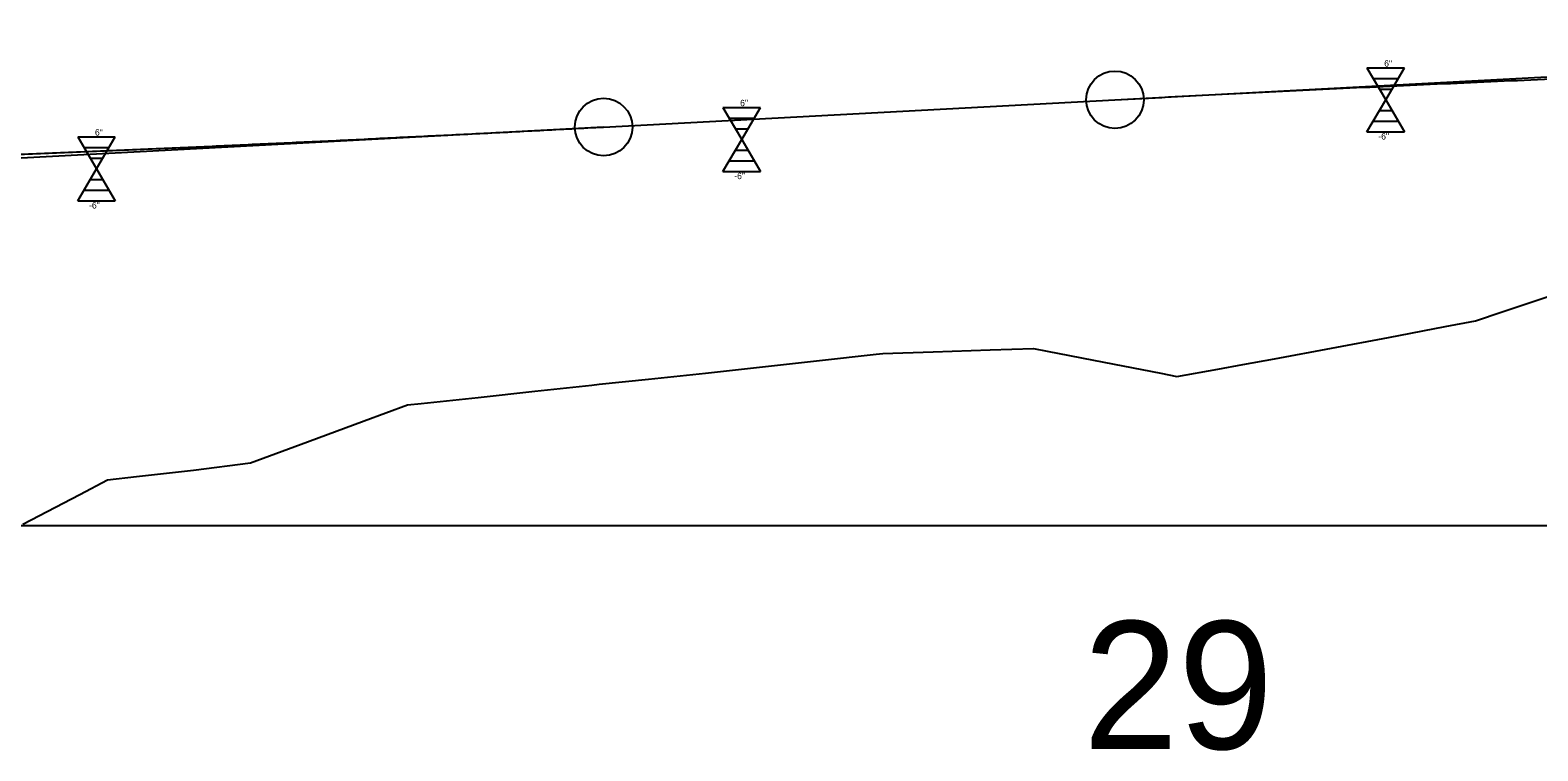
# Model space of a CAD drawing. Extents: x 573468 to 580768, y -57414 to -51768.
# Drawn here: x 575580.3 to 575698.2, y -53708.9 to -53652.5 of the extents above; entities that cross this region are included whole.
import ezdxf

# ---------------------------------------------------------------- set-up
doc = ezdxf.new("R2010")
doc.units = 0
for name, color, linetype in [('Exist Profile Cell', 7, 'Continuous'), ('Exist Vertical Profile Ground Line', 7, 'Continuous'), ('Exist Vertical Profile Horizontal Axis Label Major', 7, 'Continuous'), ('Pattern 2', 7, 'Continuous'), ('Prop Vertical Profile Curve Label', 7, 'Continuous'), ('Prop Vertical Profile Grade', 7, 'Continuous'), ('Prop VPI Label', 7, 'Continuous')]:
    doc.layers.add(name, color=color, linetype=linetype)

msp = doc.modelspace()

# ---------------------------------------------------------------- linework, layer by layer
at = {"layer": 'Exist Profile Cell'}
msp.add_line((573531.99, -53691.24), (576075.95, -53691.24), dxfattribs=at)
at = {"layer": 'Exist Vertical Profile Ground Line'}
msp.add_lwpolyline([(575579.69, -53691.16), (575584.14, -53688.82), (575586.3, -53687.68), (575588.59, -53687.43), (575593.04, -53686.93), (575597.49, -53686.34), (575601.95, -53684.71), (575606.4, -53683.07), (575609.78, -53681.8), (575610.85, -53681.7), (575615.3, -53681.23), (575619.75, -53680.75), (575624.2, -53680.26), (575624.78, -53680.19), (575628.65, -53679.79), (575633.11, -53679.32), (575637.56, -53678.84), (575642.01, -53678.34), (575646.46, -53677.84), (575646.96, -53677.78), (575650.91, -53677.66), (575655.36, -53677.51), (575658.77, -53677.39), (575659.82, -53677.6), (575664.27, -53678.48), (575668.72, -53679.34), (575669.98, -53679.58), (575673.17, -53679.01), (575675.14, -53678.66), (575677.62, -53678.21), (575682.07, -53677.38), (575686.53, -53676.54), (575690.98, -53675.69), (575693.33, -53675.23), (575695.43, -53674.53), (575699.88, -53673.04)], dxfattribs=at)
at = {"layer": 'Pattern 2'}
for p, q in [((575684.85, -53655.44), (575687.78, -53655.44)), ((575684.85, -53655.44), (575686.32, -53657.94)), ((575686.32, -53657.94), (575687.78, -53655.44)), ((575685.34, -53656.28), (575687.29, -53656.28)), ((575684.85, -53660.44), (575686.32, -53657.94)), ((575685.83, -53657.11), (575686.81, -53657.11)), ((575686.32, -53657.94), (575687.78, -53660.44)), ((575634.46, -53658.54), (575637.39, -53658.54)), ((575634.46, -53658.54), (575635.93, -53661.04)), ((575635.93, -53661.04), (575637.39, -53658.54)), ((575685.83, -53658.78), (575686.81, -53658.78)), ((575634.95, -53659.38), (575636.9, -53659.38)), ((575635.44, -53660.21), (575636.42, -53660.21)), ((575685.34, -53659.61), (575687.29, -53659.61)), ((575583.98, -53660.84), (575586.91, -53660.84)), ((575583.98, -53660.84), (575585.45, -53663.34)), ((575585.45, -53663.34), (575586.91, -53660.84)), ((575634.46, -53663.54), (575635.93, -53661.04)), ((575635.93, -53661.04), (575637.39, -53663.54)), ((575684.85, -53660.44), (575687.78, -53660.44)), ((575584.47, -53661.68), (575586.42, -53661.68)), ((575584.96, -53662.51), (575585.94, -53662.51)), ((575635.44, -53661.88), (575636.42, -53661.88)), ((575583.98, -53665.84), (575585.45, -53663.34)), ((575585.45, -53663.34), (575586.91, -53665.84)), ((575634.46, -53663.54), (575637.39, -53663.54)), ((575634.95, -53662.71), (575636.9, -53662.71)), ((575584.47, -53665.01), (575586.42, -53665.01)), ((575584.96, -53664.18), (575585.94, -53664.18)), ((575583.98, -53665.84), (575586.91, -53665.84))]:
    msp.add_line(p, q, dxfattribs=at)
at = {"layer": 'Prop Vertical Profile Curve Label'}
for centre in [(575665.13, -53657.94), (575625.13, -53660.07)]:
    msp.add_circle(centre, 2.25, dxfattribs=at)
at = {"layer": 'Prop Vertical Profile Grade'}
msp.add_line((575625.13, -53660.07), (575665.13, -53657.94), dxfattribs=at)
for points in [[(575665.13, -53657.94), (575669.33, -53657.72), (575673.53, -53657.5), (575677.73, -53657.29), (575681.93, -53657.09), (575686.13, -53656.89), (575690.33, -53656.7), (575694.53, -53656.51), (575698.73, -53656.33), (575702.93, -53656.16), (575707.13, -53655.99), (575711.33, -53655.82), (575715.53, -53655.67), (575719.73, -53655.51), (575723.93, -53655.37), (575728.13, -53655.23), (575732.33, -53655.09), (575736.53, -53654.96), (575740.73, -53654.84), (575744.93, -53654.72), (575749.13, -53654.61), (575753.33, -53654.51), (575757.53, -53654.41), (575761.73, -53654.31), (575765.93, -53654.22), (575770.13, -53654.14), (575774.33, -53654.06), (575778.53, -53653.99), (575782.73, -53653.93), (575786.93, -53653.87), (575791.13, -53653.81), (575795.33, -53653.77), (575799.53, -53653.72), (575803.73, -53653.69), (575807.93, -53653.66), (575812.13, -53653.63), (575816.33, -53653.61), (575820.53, -53653.6), (575824.73, -53653.59), (575828.93, -53653.59), (575833.13, -53653.59), (575837.33, -53653.6), (575841.53, -53653.62), (575845.73, -53653.64), (575849.93, -53653.66), (575854.13, -53653.7), (575858.33, -53653.73), (575862.53, -53653.78), (575866.73, -53653.83), (575870.93, -53653.88), (575875.13, -53653.94)], [(575375.13, -53664.65), (575380.13, -53664.73), (575385.13, -53664.8), (575390.13, -53664.87), (575395.13, -53664.93), (575400.13, -53664.98), (575405.13, -53665.02), (575410.13, -53665.06), (575415.13, -53665.09), (575420.13, -53665.11), (575425.13, -53665.13), (575430.13, -53665.14), (575435.13, -53665.14), (575440.13, -53665.14), (575445.13, -53665.13), (575450.13, -53665.11), (575455.13, -53665.08), (575460.13, -53665.05), (575465.13, -53665.01), (575470.13, -53664.97), (575475.13, -53664.91), (575480.13, -53664.85), (575485.13, -53664.79), (575490.13, -53664.71), (575495.13, -53664.63), (575500.13, -53664.54), (575505.13, -53664.45), (575510.13, -53664.34), (575515.13, -53664.24), (575520.13, -53664.12), (575525.13, -53664), (575530.13, -53663.87), (575535.13, -53663.73), (575540.13, -53663.58), (575545.13, -53663.43), (575550.13, -53663.28), (575555.13, -53663.11), (575560.13, -53662.94), (575565.13, -53662.76), (575570.13, -53662.57), (575575.13, -53662.38), (575580.13, -53662.18), (575585.13, -53661.97), (575590.13, -53661.76), (575595.13, -53661.54), (575600.13, -53661.31), (575605.13, -53661.08), (575610.13, -53660.83), (575615.13, -53660.59), (575620.13, -53660.33), (575625.13, -53660.07)]]:
    msp.add_spline(points, degree=3, dxfattribs=at)
at = {"layer": 'Prop VPI Label'}
for p, q in [((575665.13, -53657.94), (575767.39, -53652.49)), ((575625.13, -53660.07), (575502.88, -53666.58))]:
    msp.add_line(p, q, dxfattribs=at)

# ---------------------------------------------------------------- texts
at = {"layer": 'Exist Vertical Profile Horizontal Axis Label Major'}
msp.add_text('29', height=10, dxfattribs=at).set_placement((575662.64, -53708.74))
at = {"layer": 'Pattern 2'}
for s, p in [('6"', (575686.2, -53655.34)), ('6"', (575635.81, -53658.44)), ('6"', (575585.33, -53660.74)), ('-6"', (575685.74, -53661.05)), ('-6"', (575635.35, -53664.15)), ('-6"', (575584.87, -53666.45))]:
    msp.add_text(s, height=0.5, rotation=360, dxfattribs=at).set_placement(p)

doc.saveas('drawing.dxf')
